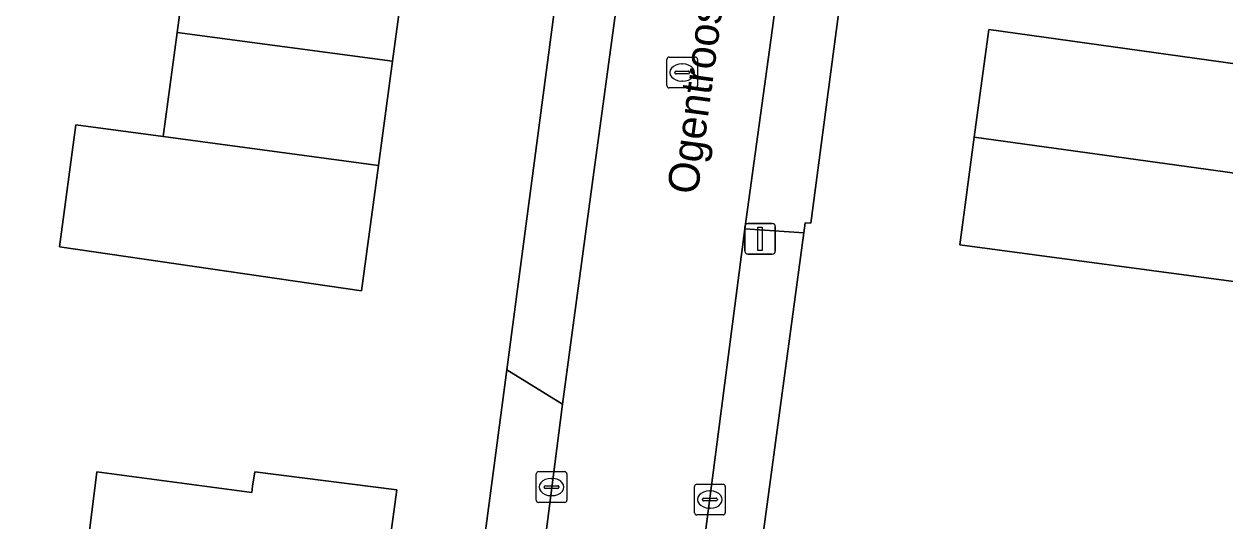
# Model space of a CAD drawing. Extents: x 161692 to 162379, y 380760 to 381678.
# Drawn here: x 162009.98 to 162049.01, y 380832.98 to 380849.13 of the extents above; entities that cross this region are included whole.
import ezdxf

# ---------------------------------------------------------------- set-up
doc = ezdxf.new("R2010")
doc.units = 0
for name, color, linetype in [('IMGEO_Erf', 7, 'Continuous'), ('IMGEO_Kolk', 7, 'Continuous'), ('IMGEO_Lichtmast', 7, 'Continuous'), ('IMGEO_Openbare_ruimte_label', 7, 'Continuous'), ('IMGEO_Pand', 7, 'Continuous'), ('IMGEO_Rijbaan_lokaal_open', 7, 'Continuous'), ('IMGEO_Rioolput', 7, 'Continuous'), ('IMGEO_Voetpad_open', 7, 'Continuous')]:
    doc.layers.add(name, color=color, linetype=linetype)

msp = doc.modelspace()

# ---------------------------------------------------------------- linework, layer by layer
at = {"layer": 'IMGEO_Erf'}
for points in [[(162040.152, 380877.602), (162037.12, 380854.554), (162035.556, 380842.662), (162035.366, 380842.674), (162035.322, 380842.349), (162031.862, 380816.692)], [(161902.994, 380830.393), (161906.216, 380829.958), (161917.567, 380828.426), (161920.64, 380828.012), (161941.489, 380825.198), (161944.559, 380824.783), (161956.36, 380823.191), (161959.367, 380822.785), (161969.747, 380821.384), (161972.782, 380820.974), (161982.64, 380819.644), (161985.956, 380819.196), (162000, 380817.301), (162003.3, 380816.856), (162006.759, 380816.389), (162007.953, 380816.216), (162010.645, 380815.865), (162022.543, 380814.259), (162025.665, 380837.887), (162027.29, 380850.188), (162027.58, 380852.385)]]:
    msp.add_lwpolyline(points, dxfattribs=at)
for points in [[(162015.392, 380852.076), (162022.383, 380851.135), (162021.951, 380847.92), (162021.494, 380844.528), (162020.947, 380840.458), (162011.13, 380841.888), (162011.664, 380845.859), (162014.504, 380845.477), (162014.959, 380848.858)], [(162053.724, 380839.019), (162050.119, 380839.504), (162050.201, 380840.114), (162050.27, 380840.627), (162040.395, 380841.955), (162040.865, 380845.455), (162041.336, 380848.955), (162051.208, 380847.577), (162054.808, 380847.075)], [(162012.342, 380834.579), (162017.378, 380833.903), (162017.407, 380834.111), (162017.474, 380834.581), (162022.092, 380833.996), (162021.579, 380830.181), (162019.676, 380830.422), (162018.387, 380820.843), (162016.301, 380821.123), (162015.851, 380820.54), (162013.714, 380820.827), (162013.445, 380821.481), (162011.443, 380821.751), (162012.11, 380826.707), (162012.129, 380826.846), (162011.39, 380826.935)]]:
    msp.add_lwpolyline(points, close=True, dxfattribs=at)
at = {"layer": 'IMGEO_Kolk'}
for p, q in [((162026.623, 380833.656), (162026.623, 380834.508)), ((162026.698, 380834.582), (162027.55, 380834.582)), ((162027.111, 380834.362), (162027.136, 380834.362)), ((162027.624, 380834.508), (162027.624, 380833.656)), ((162026.882, 380834.076), (162026.882, 380834.088)), ((162027.32, 380834.039), (162026.922, 380834.039)), ((162026.925, 380834.125), (162027.323, 380834.125)), ((162027.366, 380834.088), (162027.366, 380834.076)), ((162031.77, 380833.249), (162031.77, 380834.101)), ((162031.845, 380834.175), (162032.697, 380834.175)), ((162032.258, 380833.955), (162032.283, 380833.955)), ((162032.771, 380834.101), (162032.771, 380833.249)), ((162027.55, 380833.582), (162026.698, 380833.582)), ((162027.134, 380833.802), (162027.109, 380833.802)), ((162032.029, 380833.669), (162032.029, 380833.681)), ((162032.467, 380833.632), (162032.069, 380833.632)), ((162032.072, 380833.718), (162032.47, 380833.718)), ((162032.513, 380833.681), (162032.513, 380833.669)), ((162032.697, 380833.175), (162031.845, 380833.175)), ((162032.281, 380833.395), (162032.256, 380833.395))]:
    msp.add_line(p, q, dxfattribs=at)
for points in [[(162026.623, 380833.656), (162026.623, 380834.508)], [(162026.698, 380834.582), (162027.55, 380834.582)], [(162027.624, 380834.508), (162027.624, 380833.656)], [(162031.77, 380833.249), (162031.77, 380834.101)], [(162031.845, 380834.175), (162032.697, 380834.175)], [(162032.771, 380834.101), (162032.771, 380833.249)], [(162027.55, 380833.582), (162026.698, 380833.582)], [(162032.697, 380833.175), (162031.845, 380833.175)]]:
    msp.add_lwpolyline(points, dxfattribs=at)
for centre, radius, start, end in [((162026.7, 380834.506), 0.0765, 91.552, 178.448), ((162026.7, 380834.506), 0.0765, 91.552, 178.448), ((162027.548, 380834.506), 0.0765, 1.552, 88.448), ((162027.548, 380834.506), 0.0765, 1.552, 88.448), ((162026.922, 380834.085), 0.0403, 85.8775, 175.7526), ((162026.919, 380834.075), 0.0366, 178.938, 274.7102), ((162027.323, 380834.082), 0.043, 264.8664, 352.4533), ((162027.327, 380834.087), 0.0386, 1.7309, 96.639), ((162031.847, 380834.099), 0.0765, 91.552, 178.448), ((162031.847, 380834.099), 0.0765, 91.552, 178.448), ((162032.695, 380834.099), 0.0765, 1.552, 88.448), ((162032.695, 380834.099), 0.0765, 1.552, 88.448), ((162026.7, 380833.658), 0.0765, 181.552, 268.448), ((162026.7, 380833.658), 0.0765, 181.552, 268.448), ((162027.548, 380833.658), 0.0765, 271.552, 358.448), ((162027.548, 380833.658), 0.0765, 271.552, 358.448), ((162032.069, 380833.678), 0.0403, 85.8775, 175.7526), ((162032.066, 380833.668), 0.0366, 178.938, 274.7102), ((162032.47, 380833.675), 0.043, 264.8664, 352.4533), ((162032.474, 380833.68), 0.0386, 1.7309, 96.639), ((162031.847, 380833.251), 0.0765, 181.552, 268.448), ((162031.847, 380833.251), 0.0765, 181.552, 268.448), ((162032.695, 380833.251), 0.0765, 271.552, 358.448), ((162032.695, 380833.251), 0.0765, 271.552, 358.448)]:
    msp.add_arc(centre, radius, start, end, dxfattribs=at)
for centre, major_axis, ratio, start_param, end_param in [((162027.11, 380834.082), (-0.387, 0.002), 0.722429, 4.712389, 7.853982), ((162027.135, 380834.082), (-0.39, 0.002), 0.717154, 1.570796, 4.712389), ((162032.257, 380833.675), (-0.387, 0.002), 0.722429, 4.712389, 7.853982), ((162032.282, 380833.675), (-0.39, 0.002), 0.717154, 1.570796, 4.712389)]:
    msp.add_ellipse(centre, major_axis=major_axis, ratio=ratio, start_param=start_param, end_param=end_param, dxfattribs=at)
at = {"layer": 'IMGEO_Lichtmast'}
for p, q in [((162033.405, 380841.749), (162033.405, 380842.549)), ((162033.405, 380842.549), (162033.405, 380841.749)), ((162033.505, 380842.649), (162034.295, 380842.649)), ((162034.295, 380842.649), (162033.505, 380842.649)), ((162034.395, 380842.549), (162034.395, 380841.749)), ((162034.395, 380841.749), (162034.395, 380842.549)), ((162034.295, 380841.649), (162033.505, 380841.649)), ((162033.505, 380841.649), (162034.295, 380841.649))]:
    msp.add_line(p, q, dxfattribs=at)
msp.add_lwpolyline([(162033.825, 380842.524), (162033.975, 380842.524), (162033.975, 380841.774), (162033.825, 380841.774), (162033.825, 380842.524)], dxfattribs=at)
for centre, start, end in [((162033.505, 380842.549), 90, 180), ((162033.505, 380842.549), 90, 180), ((162034.295, 380842.549), 0, 90), ((162034.295, 380842.549), 360, 90), ((162033.505, 380841.749), 180, 270), ((162033.505, 380841.749), 180, 270), ((162034.295, 380841.749), 270, 0), ((162034.295, 380841.749), 270, 0)]:
    msp.add_arc(centre, 0.1, start, end, dxfattribs=at)
at = {"layer": 'IMGEO_Pand'}
for points in [[(162014.959, 380848.858), (162021.951, 380847.92), (162022.383, 380851.135), (162015.392, 380852.076)], [(162021.494, 380844.528), (162021.951, 380847.92), (162014.959, 380848.858), (162014.504, 380845.477)], [(162051.208, 380847.577), (162041.336, 380848.955), (162040.865, 380845.455), (162050.738, 380844.092)], [(162021.494, 380844.528), (162014.504, 380845.477), (162011.664, 380845.859), (162011.13, 380841.888), (162020.947, 380840.458)], [(162050.27, 380840.627), (162050.738, 380844.092), (162040.865, 380845.455), (162040.395, 380841.955)], [(162011.39, 380826.935), (162012.129, 380826.846), (162012.11, 380826.707), (162011.443, 380821.751), (162013.445, 380821.481), (162013.714, 380820.827), (162015.851, 380820.54), (162016.301, 380821.123), (162018.387, 380820.843), (162019.676, 380830.422), (162021.579, 380830.181), (162022.092, 380833.996), (162017.474, 380834.581), (162017.407, 380834.111), (162017.378, 380833.903), (162012.342, 380834.579)]]:
    msp.add_lwpolyline(points, close=True, dxfattribs=at)
at = {"layer": 'IMGEO_Rijbaan_lokaal_open'}
msp.add_lwpolyline([(162033.461, 380879.88), (162031.71, 380868.109), (162030.023, 380855.488), (162029.52, 380851.793), (162029.337, 380850.452), (162028.447, 380843.916), (162027.484, 380836.776), (162024.623, 380814.393), (162029.684, 380813.776), (162033.405, 380842.479), (162034.3, 380848.923), (162035.094, 380854.937), (162035.62, 380858.921), (162037.182, 380870.711), (162038.008, 380877.272)], dxfattribs=at)
at = {"layer": 'IMGEO_Rioolput'}
for p, q in [((162030.87, 380847.128), (162030.87, 380847.98)), ((162030.945, 380848.054), (162031.797, 380848.054)), ((162031.871, 380847.98), (162031.871, 380847.128)), ((162031.129, 380847.548), (162031.129, 380847.56)), ((162031.172, 380847.597), (162031.57, 380847.597)), ((162031.358, 380847.834), (162031.383, 380847.834)), ((162031.613, 380847.56), (162031.613, 380847.548)), ((162031.567, 380847.511), (162031.169, 380847.511)), ((162031.381, 380847.274), (162031.356, 380847.274)), ((162031.797, 380847.054), (162030.945, 380847.054))]:
    msp.add_line(p, q, dxfattribs=at)
for points in [[(162030.87, 380847.128), (162030.87, 380847.98)], [(162030.945, 380848.054), (162031.797, 380848.054)], [(162031.871, 380847.98), (162031.871, 380847.128)], [(162031.797, 380847.054), (162030.945, 380847.054)]]:
    msp.add_lwpolyline(points, dxfattribs=at)
for centre, radius, start, end in [((162030.947, 380847.978), 0.0765, 91.552, 178.448), ((162030.947, 380847.978), 0.0765, 91.552, 178.448), ((162031.795, 380847.978), 0.0765, 1.552, 88.448), ((162031.795, 380847.978), 0.0765, 1.552, 88.448), ((162031.169, 380847.557), 0.0403, 85.8775, 175.7526), ((162031.166, 380847.547), 0.0366, 178.938, 274.7102), ((162031.57, 380847.554), 0.043, 264.8664, 352.4533), ((162031.574, 380847.559), 0.0386, 1.7309, 96.639), ((162030.947, 380847.13), 0.0765, 181.552, 268.448), ((162030.947, 380847.13), 0.0765, 181.552, 268.448), ((162031.795, 380847.13), 0.0765, 271.552, 358.448), ((162031.795, 380847.13), 0.0765, 271.552, 358.448)]:
    msp.add_arc(centre, radius, start, end, dxfattribs=at)
for centre, major_axis, ratio, start_param, end_param in [((162031.357, 380847.554), (-0.387, 0.002), 0.722429, 4.712389, 7.853982), ((162031.382, 380847.554), (-0.39, 0.002), 0.717154, 1.570796, 4.712389)]:
    msp.add_ellipse(centre, major_axis=major_axis, ratio=ratio, start_param=start_param, end_param=end_param, dxfattribs=at)
at = {"layer": 'IMGEO_Voetpad_open'}
for points in [[(162033.405, 380842.479), (162035.322, 380842.349), (162035.366, 380842.674), (162035.556, 380842.662), (162037.12, 380854.554), (162035.094, 380854.937), (162034.3, 380848.923)], [(162027.484, 380836.776), (162028.447, 380843.916), (162029.337, 380850.452), (162027.29, 380850.188), (162025.665, 380837.887)], [(162027.484, 380836.776), (162025.665, 380837.887), (162022.543, 380814.259), (162024.623, 380814.393)]]:
    msp.add_lwpolyline(points, close=True, dxfattribs=at)
msp.add_lwpolyline([(162031.862, 380816.692), (162035.322, 380842.349), (162033.405, 380842.479), (162029.684, 380813.776), (162033.789, 380812.617), (162034.958, 380812.408), (162035.328, 380812.408)], dxfattribs=at)

# ---------------------------------------------------------------- texts
at = {"layer": 'IMGEO_Openbare_ruimte_label'}
msp.add_text('Ogentroostlaan', height=1, rotation=82.3561, dxfattribs=at).set_placement((162031.867, 380843.563))

doc.saveas('drawing.dxf')
